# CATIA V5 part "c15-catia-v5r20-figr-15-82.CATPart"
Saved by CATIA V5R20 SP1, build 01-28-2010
Part number: Part1
Bounding box of the stored display mesh (mm): x -45.183 to 59.676, y -22.214 to 29.903, z -4 to 1
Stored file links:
  D:\v5_r20\psrt_files_downloaded\c15\c15-catia-v5r20-figr-15-82.CATPart
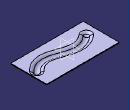
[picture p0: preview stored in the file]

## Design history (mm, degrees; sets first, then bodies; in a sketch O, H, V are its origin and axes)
SheetMetalParameters1: Thickness 1, BendRadius 5, KFactor 0.5 {= log(min(100,max(20*SheetMetalParameters1.BendRadius,SheetMetalParameters1.Thickness)/SheetMetalParameters1.Thickness))/log(100)/2}, ReliefRadialLength 1, ReliefAxialLength 2, MinimumBendRadius 0
Body1 (main body)
  Sketch1 on xy-plane, origin (0, 0, 0), H (1, 0, 0), V (0, 1, 0)
    line L1 (-45.1833, 29.903) -> (59.6761, 29.903)
    line L2 (59.6761, 29.903) -> (59.6761, -22.2137)
    line L3 (59.6761, -22.2137) -> (-45.1833, -22.2137)
    line L4 (-45.1833, -22.2137) -> (-45.1833, 29.903)
    horizontal: L1 H, L3 H
    vertical: L2 V, L4 V
  Wall1: Thickness 1, Profile Sketch1
  Sketch2 on face of Wall1, origin (0, 0, 1), H (1, 0, 0), V (0, 1, 0)
    spline S1 through (-31.3214, -3.7025) (-6.2947, 5.2247) (29.3365, -3.7025) (50.9697, 6.9251)
  d_Stamp1: Stamp_FilletRadius 4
